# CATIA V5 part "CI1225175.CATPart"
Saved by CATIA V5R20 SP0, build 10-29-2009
Part number: CI1225175
Bounding box of the stored display mesh (mm): x -24 to 24, y -20.022 to 209.5, z -27.733 to 28.158
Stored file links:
  C:\Users\Raffaele\Desktop\3D X SITO CF\BOLEX\19-INCLINED ASSEMBLY REF_CI\CI1225175.CATPart

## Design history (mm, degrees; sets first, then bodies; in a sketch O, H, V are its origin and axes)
Set1
  DatumSurface1 to DatumSurface16 "MANIFOLD_SOLID_BREP #393"
  DatumSurface17 to DatumSurface39 "MANIFOLD_SOLID_BREP #1138"
Body1 (main body)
